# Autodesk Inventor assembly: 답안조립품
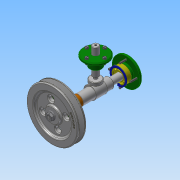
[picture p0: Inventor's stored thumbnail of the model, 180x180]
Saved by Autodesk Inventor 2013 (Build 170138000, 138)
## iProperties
Created: 2018-06
Part Number: 답안조립품
Document SubType Name: Assembly
Designer: Administrator
Author: Administrator
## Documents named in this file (19)
- C:\Users\Administrator\Desktop\480612V1007\답안조립품.iam
- C:\Users\Administrator\Desktop\480612V1007\본체.ipt
- C:\Users\Administrator\Desktop\480612V1007\V-벨트풀리.ipt
- C:\Users\Administrator\Desktop\480612V1007\너트 M8.ipt
- C:\Users\Administrator\Desktop\480612V1007\뒤커버.ipt
- C:\Users\Administrator\Desktop\480612V1007\멈춤링 15x1.ipt
- C:\Users\Administrator\Desktop\480612V1007\멈춤링 35x1.6.ipt
- 멈춤링 35x1.6.ipt
- C:\Users\Administrator\Desktop\480612V1007\베어링 6202.ipt
- 베어링 6202.ipt
- C:\Users\Administrator\Desktop\480612V1007\볼트 M4x12.ipt
- C:\Users\Administrator\Desktop\480612V1007\볼트 M4x16.ipt
- C:\Users\Administrator\Desktop\480612V1007\부시.ipt
- C:\Users\Administrator\Desktop\480612V1007\상부커버.ipt
- C:\Users\Administrator\Desktop\480612V1007\슬라이드.ipt
- C:\Users\Administrator\Desktop\480612V1007\앞커버.ipt
- C:\Users\Administrator\Desktop\480612V1007\오일 실 15 30 7.ipt
- C:\Users\Administrator\Desktop\480612V1007\키 4x4x12.ipt
- C:\Users\Administrator\Desktop\480612V1007\편심축.ipt
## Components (1 placed, 1 different names)
1. V-벨트풀리:1
